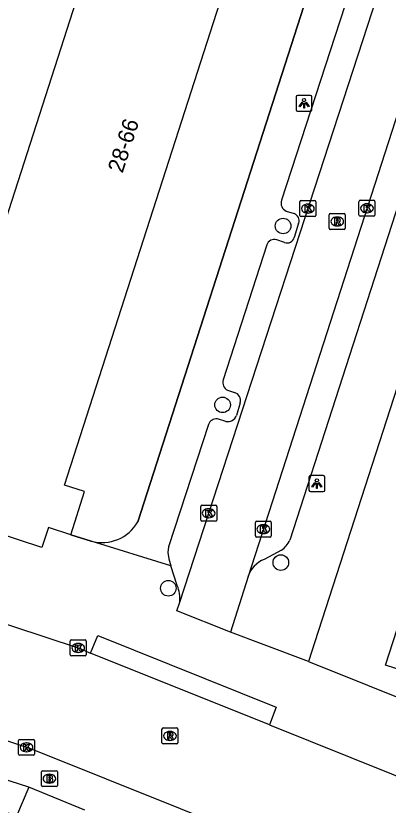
# Model space of a CAD drawing. Extents: x 162812 to 163818, y 381639 to 382470.
# Drawn here: x 163204.72 to 163228.08, y 382018.96 to 382068.45 of the extents above; entities that cross this region are included whole.
import ezdxf

# ---------------------------------------------------------------- set-up
doc = ezdxf.new("R2010")
doc.units = 0
for name, color, linetype in [('IMGEO_Boom', 7, 'Continuous'), ('IMGEO_Brandkraan', 7, 'Continuous'), ('IMGEO_Kolk', 7, 'Continuous'), ('IMGEO_Lichtpunt', 7, 'Continuous'), ('IMGEO_Muur', 7, 'Continuous'), ('IMGEO_Pand', 7, 'Continuous'), ('IMGEO_Pand_nummerreeks', 7, 'Continuous'), ('IMGEO_Rijbaan_lokaal_open', 7, 'Continuous'), ('IMGEO_Rioolput', 7, 'Continuous'), ('IMGEO_Voetpad_open', 7, 'Continuous')]:
    doc.layers.add(name, color=color, linetype=linetype)

msp = doc.modelspace()

# ---------------------------------------------------------------- linework, layer by layer
at = {"layer": 'IMGEO_Boom'}
for centre in [(163221.484, 382055.27), (163217.693, 382044.057), (163221.345, 382034.169), (163214.289, 382032.561)]:
    msp.add_circle(centre, 0.489, dxfattribs=at)
at = {"layer": 'IMGEO_Brandkraan'}
for p, q in [((163206.329, 382020.2), (163206.329, 382021.052)), ((163206.404, 382021.126), (163207.256, 382021.126)), ((163207.33, 382021.052), (163207.33, 382020.2)), ((163206.817, 382020.906), (163206.842, 382020.906)), ((163207.256, 382020.126), (163206.404, 382020.126)), ((163206.84, 382020.346), (163206.815, 382020.346))]:
    msp.add_line(p, q, dxfattribs=at)
for points in [[(163206.329, 382020.2), (163206.329, 382021.052)], [(163206.404, 382021.126), (163207.256, 382021.126)], [(163207.33, 382021.052), (163207.33, 382020.2)], [(163206.677, 382020.826), (163206.677, 382020.426), (163206.89, 382020.426)], [(163206.908, 382020.826), (163206.677, 382020.826)], [(163206.856, 382020.745), (163206.802, 382020.745), (163206.802, 382020.669)], [(163206.802, 382020.669), (163206.855, 382020.669)], [(163206.864, 382020.593), (163206.802, 382020.593), (163206.802, 382020.512)], [(163206.802, 382020.512), (163206.864, 382020.512)], [(163207.256, 382020.126), (163206.404, 382020.126)]]:
    msp.add_lwpolyline(points, dxfattribs=at)
for centre, radius, start, end in [((163206.406, 382021.05), 0.0765, 91.552, 178.448), ((163206.406, 382021.05), 0.0765, 91.552, 178.448), ((163207.254, 382021.05), 0.0765, 1.552, 88.448), ((163207.254, 382021.05), 0.0765, 1.552, 88.448), ((163206.857, 382020.707), 0.0379, 267.8285, 90.9355), ((163206.865, 382020.552), 0.0404, 269.8759, 90.5077), ((163206.896, 382020.677), 0.251, 268.6676, 293.5347), ((163206.912, 382020.681), 0.145, 59.4692, 91.5367), ((163206.937, 382020.728), 0.0922, 285.5137, 58.1501), ((163206.942, 382020.536), 0.105, 301.3115, 78.989), ((163206.406, 382020.202), 0.0765, 181.552, 268.448), ((163206.406, 382020.202), 0.0765, 181.552, 268.448), ((163207.254, 382020.202), 0.0765, 271.552, 358.448), ((163207.254, 382020.202), 0.0765, 271.552, 358.448)]:
    msp.add_arc(centre, radius, start, end, dxfattribs=at)
for centre, major_axis, ratio, start_param, end_param in [((163206.816, 382020.626), (-0.387, 0.002), 0.722429, 4.712389, 7.853982), ((163206.841, 382020.626), (-0.39, 0.002), 0.717154, 1.570796, 4.712389)]:
    msp.add_ellipse(centre, major_axis=major_axis, ratio=ratio, start_param=start_param, end_param=end_param, dxfattribs=at)
at = {"layer": 'IMGEO_Kolk'}
for p, q in [((163222.54, 382055.932), (163222.54, 382056.784)), ((163222.615, 382056.858), (163223.467, 382056.858)), ((163223.028, 382056.638), (163223.053, 382056.638)), ((163223.541, 382056.784), (163223.541, 382055.932)), ((163226.248, 382055.954), (163226.248, 382056.806)), ((163226.323, 382056.88), (163227.175, 382056.88)), ((163226.736, 382056.66), (163226.761, 382056.66)), ((163227.249, 382056.806), (163227.249, 382055.954)), ((163223.051, 382056.078), (163223.026, 382056.078)), ((163226.759, 382056.1), (163226.734, 382056.1)), ((163223.467, 382055.858), (163222.615, 382055.858)), ((163227.175, 382055.88), (163226.323, 382055.88)), ((163216.396, 382037.765), (163217.248, 382037.765)), ((163216.321, 382036.839), (163216.321, 382037.691)), ((163216.809, 382037.545), (163216.834, 382037.545)), ((163217.322, 382037.691), (163217.322, 382036.839)), ((163217.248, 382036.765), (163216.396, 382036.765)), ((163216.832, 382036.985), (163216.807, 382036.985)), ((163219.821, 382036.764), (163220.673, 382036.764)), ((163219.746, 382035.838), (163219.746, 382036.69)), ((163220.234, 382036.544), (163220.259, 382036.544)), ((163220.747, 382036.69), (163220.747, 382035.838)), ((163220.257, 382035.984), (163220.232, 382035.984)), ((163220.673, 382035.764), (163219.821, 382035.764)), ((163208.136, 382028.397), (163208.136, 382029.249)), ((163208.211, 382029.323), (163209.063, 382029.323)), ((163208.624, 382029.103), (163208.649, 382029.103)), ((163209.137, 382029.249), (163209.137, 382028.397)), ((163208.647, 382028.543), (163208.622, 382028.543)), ((163209.063, 382028.323), (163208.211, 382028.323)), ((163204.894, 382022.163), (163204.894, 382023.015)), ((163204.969, 382023.089), (163205.821, 382023.089)), ((163205.895, 382023.015), (163205.895, 382022.163)), ((163205.382, 382022.869), (163205.407, 382022.869)), ((163205.821, 382022.089), (163204.969, 382022.089)), ((163205.405, 382022.309), (163205.38, 382022.309))]:
    msp.add_line(p, q, dxfattribs=at)
for points in [[(163222.54, 382055.932), (163222.54, 382056.784)], [(163222.615, 382056.858), (163223.467, 382056.858)], [(163222.861, 382056.558), (163222.984, 382056.558), (163222.984, 382056.407), (163223.114, 382056.558), (163223.278, 382056.558), (163223.132, 382056.407), (163223.285, 382056.158), (163223.133, 382056.158), (163223.048, 382056.322), (163222.984, 382056.255), (163222.984, 382056.158), (163222.861, 382056.158), (163222.861, 382056.558)], [(163223.541, 382056.784), (163223.541, 382055.932)], [(163226.248, 382055.954), (163226.248, 382056.806)], [(163226.323, 382056.88), (163227.175, 382056.88)], [(163226.569, 382056.58), (163226.692, 382056.58), (163226.692, 382056.429), (163226.822, 382056.58), (163226.986, 382056.58), (163226.84, 382056.429), (163226.993, 382056.18), (163226.841, 382056.18), (163226.756, 382056.344), (163226.692, 382056.277), (163226.692, 382056.18), (163226.569, 382056.18), (163226.569, 382056.58)], [(163227.249, 382056.806), (163227.249, 382055.954)], [(163223.467, 382055.858), (163222.615, 382055.858)], [(163227.175, 382055.88), (163226.323, 382055.88)], [(163216.396, 382037.765), (163217.248, 382037.765)], [(163216.321, 382036.839), (163216.321, 382037.691)], [(163216.642, 382037.465), (163216.765, 382037.465), (163216.765, 382037.314), (163216.895, 382037.465), (163217.059, 382037.465), (163216.913, 382037.314), (163217.066, 382037.065), (163216.914, 382037.065), (163216.829, 382037.229), (163216.765, 382037.162), (163216.765, 382037.065), (163216.642, 382037.065), (163216.642, 382037.465)], [(163217.322, 382037.691), (163217.322, 382036.839)], [(163217.248, 382036.765), (163216.396, 382036.765)], [(163219.821, 382036.764), (163220.673, 382036.764)], [(163219.746, 382035.838), (163219.746, 382036.69)], [(163220.067, 382036.464), (163220.19, 382036.464), (163220.19, 382036.313), (163220.32, 382036.464), (163220.484, 382036.464), (163220.338, 382036.313), (163220.491, 382036.064), (163220.339, 382036.064), (163220.254, 382036.228), (163220.19, 382036.161), (163220.19, 382036.064), (163220.067, 382036.064), (163220.067, 382036.464)], [(163220.747, 382036.69), (163220.747, 382035.838)], [(163220.673, 382035.764), (163219.821, 382035.764)], [(163208.136, 382028.397), (163208.136, 382029.249)], [(163208.211, 382029.323), (163209.063, 382029.323)], [(163208.457, 382029.023), (163208.58, 382029.023), (163208.58, 382028.872), (163208.71, 382029.023), (163208.874, 382029.023), (163208.728, 382028.872), (163208.881, 382028.623), (163208.729, 382028.623), (163208.644, 382028.787), (163208.58, 382028.72), (163208.58, 382028.623), (163208.457, 382028.623), (163208.457, 382029.023)], [(163209.137, 382029.249), (163209.137, 382028.397)], [(163209.063, 382028.323), (163208.211, 382028.323)], [(163204.894, 382022.163), (163204.894, 382023.015)], [(163204.969, 382023.089), (163205.821, 382023.089)], [(163205.895, 382023.015), (163205.895, 382022.163)], [(163205.215, 382022.789), (163205.338, 382022.789), (163205.338, 382022.638), (163205.468, 382022.789), (163205.632, 382022.789), (163205.486, 382022.638), (163205.639, 382022.389), (163205.487, 382022.389), (163205.402, 382022.553), (163205.338, 382022.486), (163205.338, 382022.389), (163205.215, 382022.389), (163205.215, 382022.789)], [(163205.821, 382022.089), (163204.969, 382022.089)]]:
    msp.add_lwpolyline(points, dxfattribs=at)
for centre, start, end in [((163222.617, 382056.782), 91.552, 178.448), ((163222.617, 382056.782), 91.552, 178.448), ((163223.465, 382056.782), 1.552, 88.448), ((163223.465, 382056.782), 1.552, 88.448), ((163226.325, 382056.804), 91.552, 178.448), ((163226.325, 382056.804), 91.552, 178.448), ((163227.173, 382056.804), 1.552, 88.448), ((163227.173, 382056.804), 1.552, 88.448), ((163222.617, 382055.934), 181.552, 268.448), ((163222.617, 382055.934), 181.552, 268.448), ((163223.465, 382055.934), 271.552, 358.448), ((163223.465, 382055.934), 271.552, 358.448), ((163226.325, 382055.956), 181.552, 268.448), ((163226.325, 382055.956), 181.552, 268.448), ((163227.173, 382055.956), 271.552, 358.448), ((163227.173, 382055.956), 271.552, 358.448), ((163216.398, 382037.689), 91.552, 178.448), ((163216.398, 382037.689), 91.552, 178.448), ((163217.246, 382037.689), 1.552, 88.448), ((163217.246, 382037.689), 1.552, 88.448), ((163216.398, 382036.841), 181.552, 268.448), ((163216.398, 382036.841), 181.552, 268.448), ((163217.246, 382036.841), 271.552, 358.448), ((163217.246, 382036.841), 271.552, 358.448), ((163219.823, 382036.688), 91.552, 178.448), ((163219.823, 382036.688), 91.552, 178.448), ((163220.671, 382036.688), 1.552, 88.448), ((163220.671, 382036.688), 1.552, 88.448), ((163219.823, 382035.84), 181.552, 268.448), ((163219.823, 382035.84), 181.552, 268.448), ((163220.671, 382035.84), 271.552, 358.448), ((163220.671, 382035.84), 271.552, 358.448), ((163208.213, 382029.247), 91.552, 178.448), ((163208.213, 382029.247), 91.552, 178.448), ((163209.061, 382029.247), 1.552, 88.448), ((163209.061, 382029.247), 1.552, 88.448), ((163208.213, 382028.399), 181.552, 268.448), ((163208.213, 382028.399), 181.552, 268.448), ((163209.061, 382028.399), 271.552, 358.448), ((163209.061, 382028.399), 271.552, 358.448), ((163204.971, 382023.013), 91.552, 178.448), ((163204.971, 382023.013), 91.552, 178.448), ((163205.819, 382023.013), 1.552, 88.448), ((163205.819, 382023.013), 1.552, 88.448), ((163204.971, 382022.165), 181.552, 268.448), ((163204.971, 382022.165), 181.552, 268.448), ((163205.819, 382022.165), 271.552, 358.448), ((163205.819, 382022.165), 271.552, 358.448)]:
    msp.add_arc(centre, 0.0765, start, end, dxfattribs=at)
for centre, major_axis, ratio, start_param, end_param in [((163223.027, 382056.358), (-0.387, 0.002), 0.722429, 4.712389, 7.853982), ((163223.052, 382056.358), (-0.39, 0.002), 0.717154, 1.570796, 4.712389), ((163226.735, 382056.38), (-0.387, 0.002), 0.722429, 4.712389, 7.853982), ((163226.76, 382056.38), (-0.39, 0.002), 0.717154, 1.570796, 4.712389), ((163216.808, 382037.265), (-0.387, 0.002), 0.722429, 4.712389, 7.853982), ((163216.833, 382037.265), (-0.39, 0.002), 0.717154, 1.570796, 4.712389), ((163220.233, 382036.264), (-0.387, 0.002), 0.722429, 4.712389, 7.853982), ((163220.258, 382036.264), (-0.39, 0.002), 0.717154, 1.570796, 4.712389), ((163208.623, 382028.823), (-0.387, 0.002), 0.722429, 4.712389, 7.853982), ((163208.648, 382028.823), (-0.39, 0.002), 0.717154, 1.570796, 4.712389), ((163205.381, 382022.589), (-0.387, 0.002), 0.722429, 4.712389, 7.853982), ((163205.406, 382022.589), (-0.39, 0.002), 0.717154, 1.570796, 4.712389)]:
    msp.add_ellipse(centre, major_axis=major_axis, ratio=ratio, start_param=start_param, end_param=end_param, dxfattribs=at)
at = {"layer": 'IMGEO_Lichtpunt'}
for p, q in [((163222.302, 382063.362), (163222.302, 382062.555)), ((163222.302, 382063.362), (163222.302, 382062.555)), ((163223.204, 382063.457), (163222.396, 382063.457)), ((163223.204, 382063.457), (163222.396, 382063.457)), ((163223.298, 382062.555), (163223.298, 382063.362)), ((163223.298, 382062.555), (163223.298, 382063.362)), ((163222.396, 382062.461), (163223.204, 382062.461)), ((163222.396, 382062.461), (163223.204, 382062.461)), ((163223.108, 382039.524), (163223.108, 382038.717)), ((163223.108, 382039.524), (163223.108, 382038.717)), ((163224.01, 382039.619), (163223.202, 382039.619)), ((163224.01, 382039.619), (163223.202, 382039.619)), ((163224.104, 382038.717), (163224.104, 382039.524)), ((163224.104, 382038.717), (163224.104, 382039.524)), ((163223.202, 382038.623), (163224.01, 382038.623)), ((163223.202, 382038.623), (163224.01, 382038.623))]:
    msp.add_line(p, q, dxfattribs=at)
for points in [[(163222.676, 382063.026), (163222.715, 382062.998), (163222.527, 382062.736), (163222.489, 382062.763), (163222.676, 382063.026)], [(163222.888, 382062.998), (163222.926, 382063.025), (163223.113, 382062.763), (163223.074, 382062.735), (163222.888, 382062.998)], [(163222.778, 382062.978), (163222.825, 382062.978), (163222.825, 382062.656), (163222.778, 382062.656), (163222.778, 382062.978)], [(163223.482, 382039.188), (163223.521, 382039.16), (163223.333, 382038.898), (163223.295, 382038.925), (163223.482, 382039.188)], [(163223.584, 382039.14), (163223.631, 382039.14), (163223.631, 382038.818), (163223.584, 382038.818), (163223.584, 382039.14)], [(163223.694, 382039.16), (163223.732, 382039.187), (163223.919, 382038.925), (163223.88, 382038.897), (163223.694, 382039.16)]]:
    msp.add_lwpolyline(points, dxfattribs=at)
for centre in [(163222.801, 382063.16), (163223.607, 382039.322)]:
    msp.add_circle(centre, 0.0994, dxfattribs=at)
for centre, start, end in [((163222.396, 382063.362), 90, 180), ((163222.396, 382063.362), 90, 180), ((163223.204, 382063.362), 0, 90), ((163223.204, 382063.362), 0, 90), ((163222.396, 382062.555), 180, 270), ((163222.396, 382062.555), 180, 270), ((163223.204, 382062.555), 270, 0), ((163223.204, 382062.555), 270, 360), ((163223.202, 382039.524), 90, 180), ((163223.202, 382039.524), 90, 180), ((163224.01, 382039.524), 0, 90), ((163224.01, 382039.524), 0, 90), ((163223.202, 382038.717), 180, 270), ((163223.202, 382038.717), 180, 270), ((163224.01, 382038.717), 270, 0), ((163224.01, 382038.717), 270, 360)]:
    msp.add_arc(centre, 0.0946, start, end, dxfattribs=at)
at = {"layer": 'IMGEO_Muur'}
for points in [[(163226.318, 382080.043), (163212.368, 382036.722)], [(163208.165, 382035.907), (163209.453, 382035.511)]]:
    msp.add_lwpolyline(points, dxfattribs=at)
msp.add_arc((163210.127, 382038.003), 2.582, 254.8709, 330.2488, dxfattribs=at)
at = {"layer": 'IMGEO_Pand'}
for points in [[(163213.268, 382084.245), (163198.696, 382038.994)], [(163208.165, 382035.907), (163209.039, 382038.621), (163207.78, 382039.026), (163221.488, 382081.598), (163222.696, 382081.21)], [(163208.165, 382035.907), (163206.762, 382036.359), (163206.362, 382035.122), (163201.882, 382036.573), (163202.291, 382037.836), (163198.696, 382038.994)], [(163237.096, 382031.409), (163236.699, 382030.171), (163235.17, 382025.41), (163234.993, 382025.467), (163227.919, 382027.738), (163229.845, 382033.737)]]:
    msp.add_lwpolyline(points, dxfattribs=at)
at = {"layer": 'IMGEO_Rijbaan_lokaal_open'}
for points in [[(163232.808, 382075.129), (163219.286, 382033.294)], [(163215.005, 382031.688), (163227.986, 382071.536)], [(163219.286, 382033.294), (163218.19, 382029.798)], [(163200.444, 382031.53), (163208.637, 382028.823), (163209.414, 382028.496)], [(163218.19, 382029.798), (163214.829, 382031.148), (163215.005, 382031.688)], [(163220.636, 382023.993), (163209.414, 382028.496)], [(163198.267, 382024.955), (163205.64, 382022.508), (163238.551, 382009.339)], [(163220.636, 382023.993), (163241.137, 382015.775)]]:
    msp.add_lwpolyline(points, dxfattribs=at)
at = {"layer": 'IMGEO_Rioolput'}
for p, q in [((163224.384, 382055.124), (163224.384, 382055.976)), ((163224.459, 382056.05), (163225.311, 382056.05)), ((163224.872, 382055.83), (163224.897, 382055.83)), ((163225.385, 382055.976), (163225.385, 382055.124)), ((163224.895, 382055.27), (163224.87, 382055.27)), ((163225.311, 382055.05), (163224.459, 382055.05)), ((163213.89, 382022.88), (163213.89, 382023.732)), ((163213.965, 382023.806), (163214.817, 382023.806)), ((163214.378, 382023.586), (163214.403, 382023.586)), ((163214.891, 382023.732), (163214.891, 382022.88)), ((163214.401, 382023.026), (163214.376, 382023.026)), ((163214.817, 382022.806), (163213.965, 382022.806))]:
    msp.add_line(p, q, dxfattribs=at)
for points in [[(163224.384, 382055.124), (163224.384, 382055.976)], [(163224.459, 382056.05), (163225.311, 382056.05)], [(163224.973, 382055.748), (163224.721, 382055.75), (163224.721, 382055.35)], [(163224.899, 382055.669), (163224.845, 382055.669), (163224.845, 382055.588)], [(163224.845, 382055.588), (163224.897, 382055.588)], [(163225.385, 382055.976), (163225.385, 382055.124)], [(163224.721, 382055.35), (163224.845, 382055.35), (163224.845, 382055.512), (163224.856, 382055.512)], [(163224.903, 382055.483), (163224.974, 382055.35), (163225.114, 382055.35), (163225.049, 382055.476)], [(163225.311, 382055.05), (163224.459, 382055.05)], [(163213.89, 382022.88), (163213.89, 382023.732)], [(163213.965, 382023.806), (163214.817, 382023.806)], [(163214.479, 382023.504), (163214.227, 382023.506), (163214.227, 382023.106)], [(163214.405, 382023.425), (163214.351, 382023.425), (163214.351, 382023.344)], [(163214.891, 382023.732), (163214.891, 382022.88)], [(163214.227, 382023.106), (163214.351, 382023.106), (163214.351, 382023.268), (163214.362, 382023.268)], [(163214.351, 382023.344), (163214.403, 382023.344)], [(163214.409, 382023.239), (163214.48, 382023.106), (163214.62, 382023.106), (163214.555, 382023.232)], [(163214.817, 382022.806), (163213.965, 382022.806)]]:
    msp.add_lwpolyline(points, dxfattribs=at)
for centre, radius, start, end in [((163224.461, 382055.974), 0.0765, 91.552, 178.448), ((163224.461, 382055.974), 0.0765, 91.552, 178.448), ((163224.881, 382055.777), 0.19, 274.7715, 282.9687), ((163224.905, 382055.573), 0.0964, 77.0061, 93.1865), ((163224.919, 382055.63), 0.0378, 276.6634, 79.6772), ((163224.972, 382055.638), 0.109, 350.3612, 89.416), ((163224.97, 382055.638), 0.112, 277.5842, 350.9817), ((163225.309, 382055.974), 0.0765, 1.552, 88.448), ((163225.309, 382055.974), 0.0765, 1.552, 88.448), ((163224.461, 382055.126), 0.0765, 181.552, 268.448), ((163224.461, 382055.126), 0.0765, 181.552, 268.448), ((163224.855, 382055.459), 0.0533, 26.0293, 88.6989), ((163224.954, 382055.423), 0.108, 29.5134, 73.7905), ((163225.309, 382055.126), 0.0765, 271.552, 358.448), ((163225.309, 382055.126), 0.0765, 271.552, 358.448), ((163213.967, 382023.73), 0.0765, 91.552, 178.448), ((163213.967, 382023.73), 0.0765, 91.552, 178.448), ((163214.411, 382023.329), 0.0964, 77.0061, 93.1865), ((163214.425, 382023.386), 0.0378, 276.6634, 79.6772), ((163214.478, 382023.394), 0.109, 350.3612, 89.416), ((163214.815, 382023.73), 0.0765, 1.552, 88.448), ((163214.815, 382023.73), 0.0765, 1.552, 88.448), ((163214.361, 382023.215), 0.0533, 26.0293, 88.6989), ((163214.387, 382023.533), 0.19, 274.7715, 282.9687), ((163214.476, 382023.394), 0.112, 277.5842, 350.9817), ((163214.46, 382023.179), 0.108, 29.5134, 73.7905), ((163213.967, 382022.882), 0.0765, 181.552, 268.448), ((163213.967, 382022.882), 0.0765, 181.552, 268.448), ((163214.815, 382022.882), 0.0765, 271.552, 358.448), ((163214.815, 382022.882), 0.0765, 271.552, 358.448)]:
    msp.add_arc(centre, radius, start, end, dxfattribs=at)
for centre, major_axis, ratio, start_param, end_param in [((163224.871, 382055.55), (-0.387, 0.002), 0.722429, 4.712389, 7.853982), ((163224.896, 382055.55), (-0.39, 0.002), 0.717154, 1.570796, 4.712389), ((163214.377, 382023.306), (-0.387, 0.002), 0.722429, 4.712389, 7.853982), ((163214.402, 382023.306), (-0.39, 0.002), 0.717154, 1.570796, 4.712389)]:
    msp.add_ellipse(centre, major_axis=major_axis, ratio=ratio, start_param=start_param, end_param=end_param, dxfattribs=at)
at = {"layer": 'IMGEO_Voetpad_open'}
for points in [[(163212.368, 382036.722), (163226.318, 382080.043)], [(163225.353, 382069.07), (163221.392, 382056.88)], [(163230.501, 382062.143), (163221.906, 382035.578)], [(163221.678, 382056.2), (163222.177, 382056.062)], [(163222.463, 382055.436), (163222.187, 382054.553)], [(163220.457, 382054.085), (163217.719, 382045.617)], [(163221.584, 382054.225), (163221.089, 382054.405)], [(163229.54, 382047.945), (163223.488, 382029.202), (163223.089, 382027.966)], [(163218.005, 382044.974), (163218.436, 382044.831)], [(163218.787, 382044.184), (163218.557, 382043.397)], [(163216.804, 382042.833), (163214.289, 382035.166), (163214.259, 382034.808), (163214.314, 382034.401), (163214.452, 382033.974)], [(163217.891, 382043.019), (163217.366, 382043.177)], [(163209.453, 382035.511), (163208.165, 382035.907)], [(163214.452, 382033.974), (163209.453, 382035.511)], [(163221.384, 382034.947), (163220.308, 382034.371)], [(163214.849, 382032.74), (163214.452, 382033.974)], [(163209.414, 382028.496), (163209.865, 382029.593), (163221.055, 382025.109), (163220.636, 382023.993)], [(163223.089, 382027.966), (163220.309, 382029.005), (163218.19, 382029.798)], [(163223.089, 382027.966), (163234.283, 382023.476), (163257.35, 382014.223), (163260.414, 382012.994)], [(163205.535, 382020.087), (163184.822, 382026.746)], [(163205.535, 382020.087), (163204.774, 382018.279), (163202.855, 382018.967)], [(163209.059, 382018.648), (163205.535, 382020.087)]]:
    msp.add_lwpolyline(points, dxfattribs=at)
for centre, radius, start, end in [((163221.895, 382056.692), 0.537, 159.4761, 246.146), ((163221.983, 382055.595), 0.506, 341.6707, 67.4376), ((163220.937, 382053.922), 0.506, 72.4807, 161.2281), ((163221.731, 382054.674), 0.472, 251.9233, 345.1644), ((163218.272, 382045.478), 0.57, 165.8687, 242.0893), ((163218.312, 382044.345), 0.501, 341.2635, 75.6965), ((163218.023, 382043.562), 0.559, 256.3211, 342.8346), ((163217.316, 382042.627), 0.552, 84.8335, 158.1081), ((163210.127, 382038.003), 2.582, 254.8709, 330.2488), ((163220.552, 382036.166), 1.476, 304.2927, 336.5082), ((163220.958, 382032.731), 1.765, 111.6214, 161.3805), ((163212.8, 382031.899), 2.215, 354.5445, 22.3252)]:
    msp.add_arc(centre, radius, start, end, dxfattribs=at)

# ---------------------------------------------------------------- texts
at = {"layer": 'IMGEO_Pand_nummerreeks'}
msp.add_text('28-66', height=1, rotation=72.1517, dxfattribs=at).set_placement((163211.415, 382058.537))

doc.saveas('drawing.dxf')
